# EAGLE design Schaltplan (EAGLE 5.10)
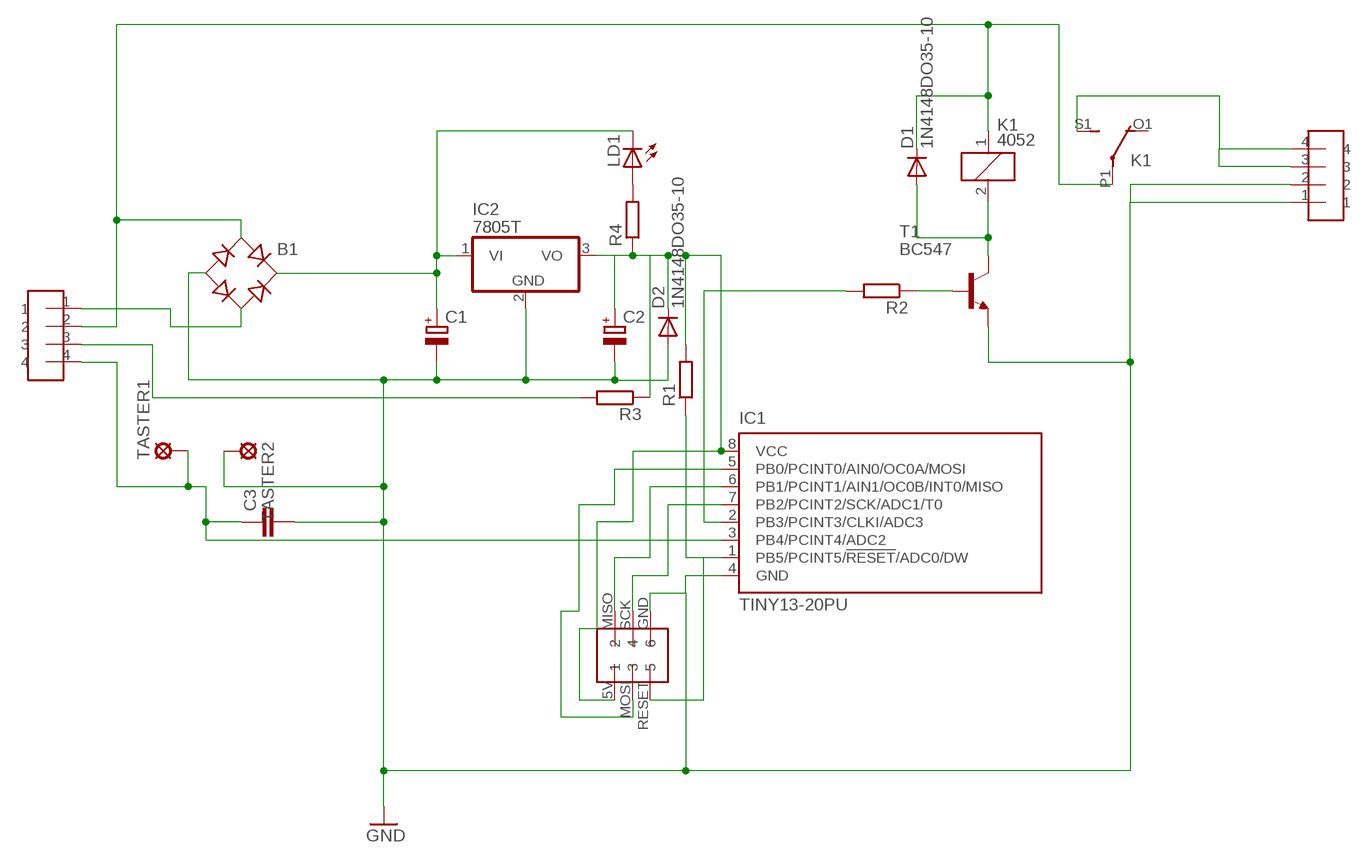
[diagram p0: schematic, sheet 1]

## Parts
B1  B-DIL  [B-DIL]
C1  CPOL-EUE5-13  [E5-13]
C2  CPOL-EUE5-13  [E5-13]
C3  C-EU050-035X075  [C050-035X075]
D1  1N4148DO35-10  [DO35-10]
D2  1N4148DO35-10  [DO35-10]
IC1  TINY13-20PU  [DIL08]
IC2  7805T  [TO220H]
K1  4052  [F4052]
LD1  LED5MM  [LED5MM]
R1  R-EU_0207/12  [0207/12]
R2  R-EU_0207/12  [0207/12]
R3  R-EU_0207/12  [0207/12]
R4  R-EU_0207/12  [0207/12]
T1  BC547  [TO92]
TASTER1  LSP10  [LSP10]
TASTER2  LSP10  [LSP10]
U$1  WANNENSTECKER6POL  [WANNENSTECKER6POL]
U$2  BUCHSE4POL  [BUCHSE4POL]
U$3  BUCHSE4POL  [BUCHSE4POL]

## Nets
GND: B1.- C1.- C2.- C3.2 D2.A IC1.4(GND) IC2.2(GND) T1.1(E) TASTER2.MP U$1.GND U$3.1 U$3.2
N$1: IC1.6(PB1/PCINT1/AIN1/OC0B/INT0/MISO) U$1.MISO
N$2: IC1.7(PB2/PCINT2/SCK/ADC1/T0) U$1.SCK
N$4: C2.+ D2.C IC1.8(VCC) IC2.3(VO) R1.2 R3.1 R4.1 U$1.5V
N$5: IC1.5(PB0/PCINT0/AIN0/OC0A/MOSI) U$1.MOSI
N$6: IC1.1(PB5/PCINT5/!RESET!/ADC0/DW) R1.1 U$1.RESET
N$7: B1.+ C1.+ IC2.1(VI) LD1.K(C)
N$8: B1.AC2 U$2.1
N$11: C3.1 IC1.3(PB4/PCINT4/ADC2) TASTER1.MP U$2.4
N$12: B1.AC1 D1.C K1.1 K1.P1(2:P) U$2.2
N$15: D1.A K1.2 T1.3(C)
N$16: R2.1 T1.2(B)
N$17: IC1.2(PB3/PCINT3/CLKI/ADC3) R2.2
N$18: K1.S1(2:S) U$3.3 U$3.4
N$19: R3.2 U$2.3
N$20: LD1.A R4.2
Unconnected: K1.O1(2:O) K1.O2(3:O) K1.P2(3:P) K1.S2(3:S)

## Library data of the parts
B1 = rectifier:B-DIL: RECTIFIER
C1 C2 = rcl:CPOL-EU: POLARIZED CAPACITOR, European symbol
C3 = resistor:C-EU: CAPACITOR, European symbol
D1 D2 = diode:1N4148: DIODE
IC1 = atmel:TINY13: 8-bit AVR Microcontroller with 1K Bytes In-System Programmable Flash Source: http://www.atmel.com/dyn/resources/prod_documents/2535S.pdf; MPN: ATTINY13-20PU; OC_FARNELL: 9171550; OC_NEWARK: 96K6521
IC2 = linear2:78*: Positive VOLTAGE REGULATOR
K1 = relay:4052: RELAY 2 x switch, Finder; OC_FARNELL: unknown; OC_NEWARK: unknown
LD1 = led:LED: LED
R1-R4 = rcl:R-EU_: RESISTOR, European symbol
T1 = transistor:BC547: NPN TRANSISTOR
TASTER1 TASTER2 = solpad:LSP10: SOLDER PAD
U$1 = Wannenstecker6pol:WANNENSTECKER6POL: WSL 6G :: Wannenstecker, 6-polig, gerade Allgemeines Typ Wannenstecker Polzahl 6 Aufbau gerade Material vergoldete Kontakte Maße Rastermaß 2,54 mm
U$2 U$3 = Buchse4pol:BUCHSE4POL

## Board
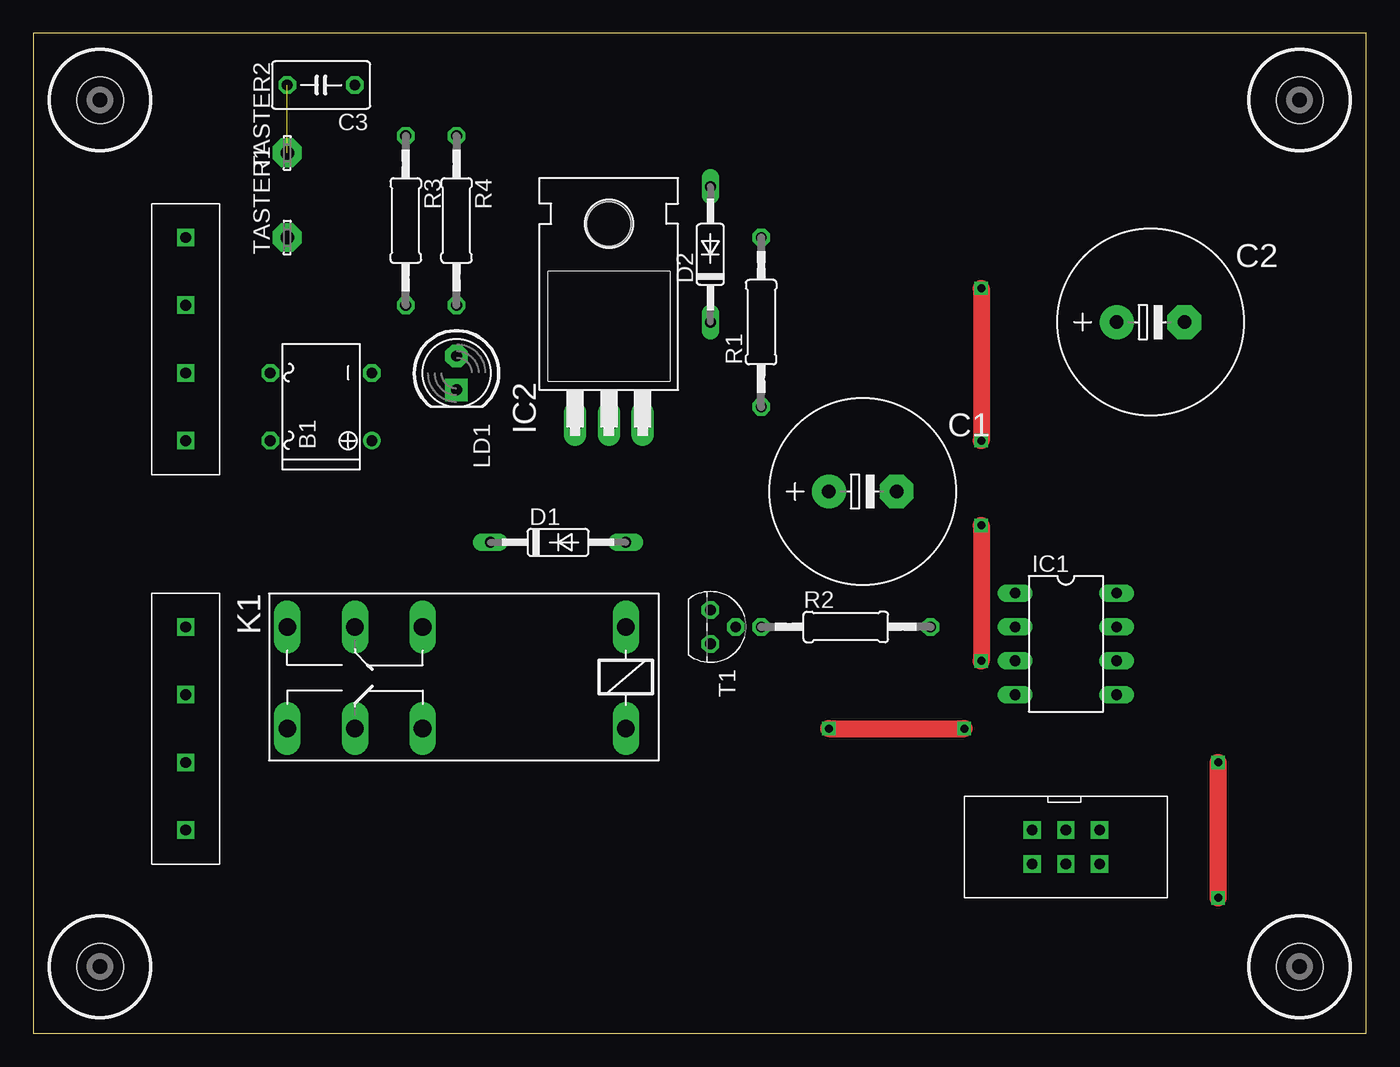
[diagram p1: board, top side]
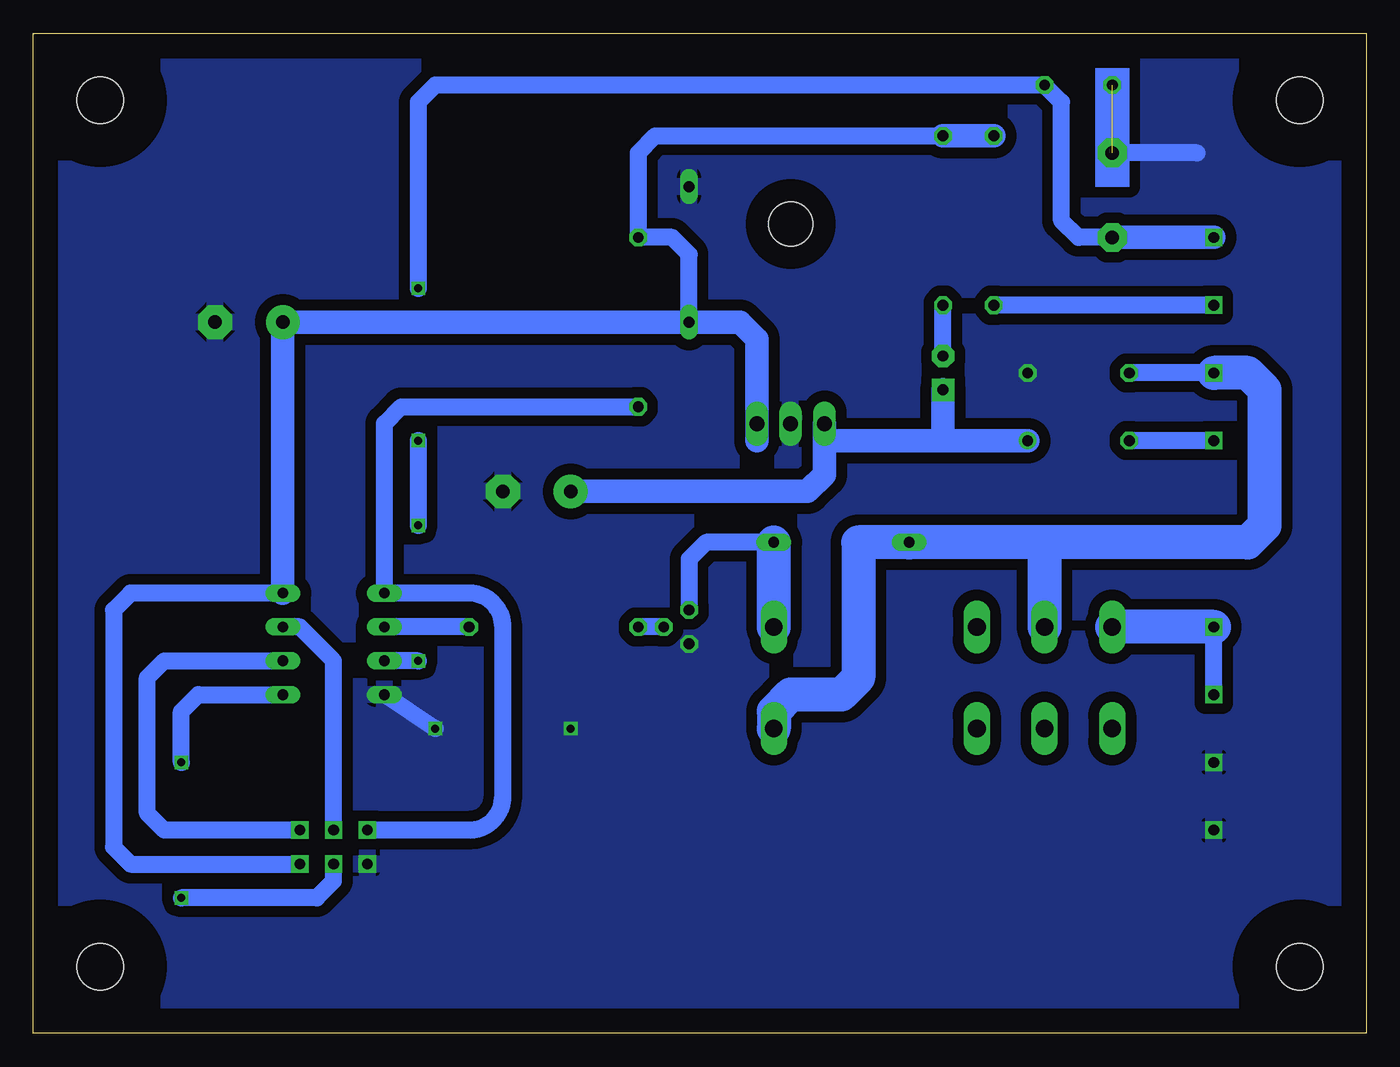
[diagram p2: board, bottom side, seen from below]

Size 100 x 75 mm. Coordinates in mm from the lower left corner, seen from the top.
Outline: 0,0 100,0 100,75 0,75 0,0
Copper layers (1*16): Top 0.035mm / dielectric 1.5mm / Bottom 0.035mm
Design rules "default": minimum track width 10mil, minimum drill 24mil, track to track 8mil, track to pad 8mil, pad to pad 8mil, via to via 8mil, smd to smd 8mil, copper to edge 40mil, drill to drill 8mil, minimum pad ring 10mil, minimum via ring 8mil, stop-mask expansion 4mil, vias tented up to drill 0mil, thermal gap 10mil

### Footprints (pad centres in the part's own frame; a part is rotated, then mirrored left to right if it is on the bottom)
B-DIL = drill 0.813 round: + -2.54,-3.81 | drill 0.813 octagon: - 2.54,-3.81; AC1 2.54,3.81; AC2 -2.54,3.81
E5-13 = drill 1.016 pad 2.54 round: + -2.54,0 | drill 1.016 pad 2.54 octagon: - 2.54,0
C050-035X075 = drill 0.813 octagon: 1 -2.54,0; 2 2.54,0
DO35-10 = drill 0.813 long: A 5.08,0; C -5.08,0
DIL08 = drill 0.813 long: 1 -3.81,-3.81; 2 -1.27,-3.81; 3 1.27,-3.81; 4 3.81,-3.81; 5 3.81,3.81; 6 1.27,3.81; 7 -1.27,3.81; 8 -3.81,3.81
TO220H = drill 1.118 long: 1 -2.54,-10.16; 2 0,-10.16; 3 2.54,-10.16 | hole 3.302: 0,4.826
F4052 = drill 1.321 long: 1 -3.81,3.81; 2 -3.81,-3.81; O1 11.43,-3.81; O2 11.43,3.81; P1 16.51,-3.81; P2 16.51,3.81; S1 21.59,-3.81; S2 21.59,3.81
LED5MM = drill 0.813 pad 1.676 octagon: A -1.27,0 | drill 0.813 pad 1.676 square: K 1.27,0
0207/12 = drill 0.813 octagon: 1 -6.35,0; 2 6.35,0
TO92 = drill 0.813 octagon: 1 1.27,0; 2 0,1.905; 3 -1.27,0
LSP10 = drill 1.016 pad 2.159 octagon: MP 0,0
WANNENSTECKER6POL = drill 0.8 square: 5V 0,2.54; GND 5.08,2.54; MISO 0,0; MOSI 2.54,2.54; RESET 5.08,0; SCK 2.54,0
BUCHSE4POL = drill 0.8 square: 1 2.54,2.54; 2 7.62,2.54; 3 12.7,2.54; 4 17.78,2.54
DRIL-3,5 = hole 3.5: 0,0

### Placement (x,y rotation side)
B1  21.59,46.99 90 top
C1  62.23,40.64 0 top
C2  83.82,53.34 0 top
C3  21.59,71.12 180 top
D1  39.37,36.83 0 top
D2  50.8,58.42 90 top
IC1  77.47,29.21 270 top
IC2  43.18,55.88 0 top
K1  40.64,26.67 180 top
LD1  31.75,49.53 270 top
R1  54.61,53.34 90 top
R2  60.96,30.48 0 top
R3  27.94,60.96 270 top
R4  31.75,60.96 270 top
T1  50.8,30.48 270 top
TASTER1  19.05,59.69 90 top
TASTER2  19.05,66.04 90 top
U$1  80.01,15.24 180 top
U$2  13.97,41.91 90 top
U$3  13.97,12.7 90 top
U$4  [DRIL-3,5]  5,70 0 top
U$5  [DRIL-3,5]  95,70 0 top
U$6  [DRIL-3,5]  95,5 0 top
U$7  [DRIL-3,5]  5,5 0 top

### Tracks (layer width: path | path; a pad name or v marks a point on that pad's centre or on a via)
GND  (via drill 0.6)  (1 unrouted)
  Top 1.27: v59.69,22.86 v69.85,22.86
  Bottom 1.27: 12.7,66.04 TASTER2.MP | v69.85,22.86 IC1.4
  pour Bottom (isolate 0.813): 2.5,72.5 2.5,2.5 97.5,2.5 97.5,72.5
N$1
  Bottom 1.27: IC1.6 90.17,27.94 91.44,26.67 91.44,16.51 90.17,15.24 U$1.MISO
N$2
  Bottom 1.27: U$1.SCK 77.47,27.94 80.01,30.48 IC1.7
N$4
  Bottom 1.27: U$1.5V 92.71,12.7 93.98,13.97 93.98,31.75 92.71,33.02 IC1.8 | R4.1 53.34,67.31 54.61,66.04 R1.2 52.07,59.69 50.8,58.42 D2.C
  Bottom 1.778: R4.1 R3.1 | IC1.8 C2.+ D2.C 46.99,53.34 45.72,52.07 IC2.3 45.72,44.45
N$5  (via drill 0.6)
  Top 1.27: v88.9,10.16 v88.9,20.32
  Bottom 1.27: U$1.MOSI 77.47,11.43 78.74,10.16 v88.9,10.16 | v88.9,20.32 88.9,24.13 87.63,25.4 IC1.5
N$6
  Bottom 1.27: R1.1 72.39,46.99 73.66,45.72 IC1.1 67.31,33.02 arc90 64.77,30.48 64.77,17.78 arc90 67.31,15.24 U$1.RESET
N$7
  Bottom 1.778: B1.+ 31.75,44.45 | 31.75,44.45 LD1.K | 31.75,44.45 40.64,44.45 IC2.1 40.64,41.91 41.91,40.64 C1.+
N$8
  Bottom 1.27: U$2.1 B1.AC2
N$11  (via drill 0.6)
  Top 1.27: v71.12,38.1 v71.12,27.94 | v71.12,55.88 v71.12,44.45
  Bottom 1.27: v71.12,27.94 IC1.3 | v71.12,44.45 v71.12,38.1 | v71.12,55.88 71.12,69.85 69.85,71.12 C3.1 22.86,69.85 22.86,60.96 21.59,59.69 TASTER1.MP
  Bottom 1.778: U$2.4 TASTER1.MP
N$12
  Bottom 1.27: U$2.2 B1.AC1
  Bottom 2.54: U$2.2 8.89,49.53 7.62,48.26 7.62,38.1 8.89,36.83 24.13,36.83 | K1.1 44.45,24.13 43.18,25.4 39.37,25.4 38.1,26.67 38.1,36.83 D1.C 24.13,36.83 | 24.13,36.83 K1.P1
N$15
  Bottom 1.27: T1.3 50.8,35.56 49.53,36.83 D1.A
  Bottom 2.54: K1.2 D1.A
N$16
  Bottom 1.27: T1.2 R2.1
N$17
  Bottom 1.27: R2.2 IC1.2
N$18
  Bottom 1.27: U$3.3 U$3.4
  Bottom 2.54: U$3.4 K1.S1
N$19
  Bottom 1.27: U$2.3 R3.2
N$20
  Bottom 1.27: LD1.A R4.2
(copper drawn outside any net)
  shapes: Bottom area x1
